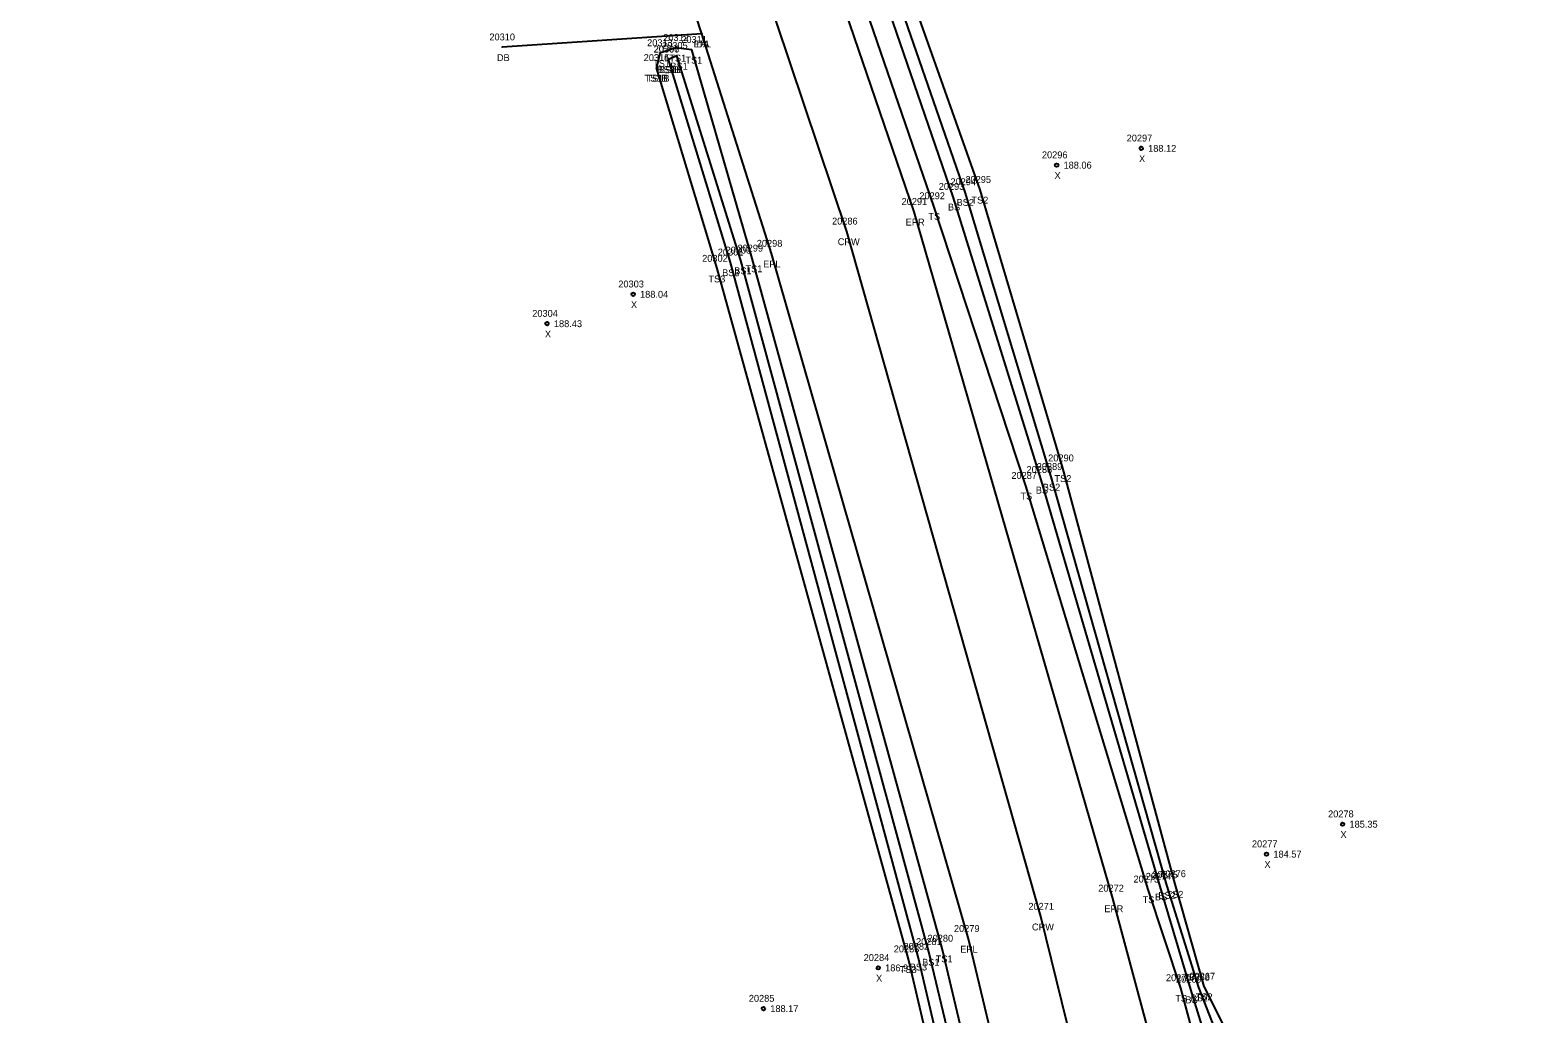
# Model space of a CAD drawing. Extents: x 2077883 to 2078272, y 787819 to 788945.
# Drawn here: x 2077915.3 to 2078134.4, y 788522.7 to 788665.6 of the extents above; entities that cross this region are included whole.
import ezdxf

# ---------------------------------------------------------------- set-up
doc = ezdxf.new("R2010")
doc.units = 0
for name, color, linetype in [('RD_DTM_BkLn1', 7, 'Continuous'), ('RD_DTM_BkLn2', 7, 'Continuous'), ('RD_EX_Driveway', 7, 'Continuous'), ('RD_EX_Driveway_txCode', 7, 'Continuous'), ('RD_EX_Road', 7, 'Continuous'), ('RD_EX_Road_txCode', 7, 'Continuous'), ('RD_Sketch8', 7, 'Continuous'), ('RD_SMD_Locator', 7, 'Continuous'), ('RD_SMD_Misc', 7, 'Continuous')]:
    doc.layers.add(name, color=color, linetype=linetype)

msp = doc.modelspace()

# ---------------------------------------------------------------- linework, layer by layer
at = {"layer": 'RD_DTM_BkLn1'}
msp.add_lwpolyline([(2078089.54, 788425.19), (2078086.71, 788437.21), (2078062.2, 788536.79), (2078033.97, 788636.37), (2078001.1, 788734.32), (2077964.77, 788830.93), (2077924.88, 788926.7)], dxfattribs=at)
at = {"layer": 'RD_DTM_BkLn2'}
for points in [[(2078132.44, 788472.19), (2078118.34, 788466.81), (2078100.1, 788488.15), (2078085.17, 788526.48), (2078080.48, 788541.38), (2078063.7, 788600.7), (2078051.16, 788642.09), (2078017.07, 788740.46), (2077982.21, 788837.85), (2077942.69, 788934.33)], [(2078130.39, 788474.32), (2078119.21, 788468.58), (2078104.21, 788490.29), (2078085.93, 788526.63), (2078081.69, 788541.53), (2078065.4, 788601.95), (2078053.34, 788642.42), (2078018.45, 788740.81), (2077983.36, 788838.44), (2077944.78, 788934.86)], [(2078134.43, 788470.29), (2078120, 788457.99), (2078107.89, 788457.91), (2078093.72, 788484.84), (2078082.52, 788526.41), (2078077.77, 788540.75), (2078060.01, 788599.41), (2078046.63, 788640.05), (2078012.72, 788738.62), (2077977.66, 788835.93), (2077936.62, 788932.18)], [(2078133.54, 788471.13), (2078119.08, 788459.82), (2078109.91, 788458.97), (2078096.37, 788486), (2078083.98, 788526.2), (2078079.55, 788541.15), (2078062.23, 788600.27), (2078049.45, 788641.41), (2078015.58, 788739.83), (2077979.12, 788836.63), (2077939.6, 788933.24)], [(2078073.43, 788440.66), (2078068.04, 788445.98), (2078067.07, 788450.97), (2078047.86, 788532.15), (2078020.2, 788632.44), (2078011.47, 788662.76), (2078009.13, 788663.05), (2078006.78, 788662.29), (2078006.29, 788660.13)], [(2078061.84, 788450.02), (2078042.92, 788530.6), (2078015.11, 788630.96), (2078006.29, 788660.13)], [(2078065.37, 788450.21), (2078045.88, 788531.66), (2078018.55, 788632.15), (2078009.27, 788661.89), (2078008.07, 788661.37)], [(2078065.33, 788432.61), (2078063.14, 788450.63), (2078044.34, 788530.97), (2078017.09, 788631.87), (2078008.07, 788661.37)]]:
    msp.add_lwpolyline(points, dxfattribs=at)
at = {"layer": 'RD_EX_Driveway'}
msp.add_line((2078012.91, 788665.11), (2077983.89, 788663.13), dxfattribs=at)
at = {"layer": 'RD_EX_Road'}
for points in [[(2078107.13, 788420.86), (2078105.11, 788427.29), (2078111.84, 788429.2), (2078117.69, 788434.7), (2078115.66, 788443.13), (2078106.49, 788447.64), (2078097.77, 788449.71), (2078094.97, 788456.34), (2078072.64, 788539.43), (2078043.77, 788639.22), (2078010.2, 788737.35), (2077974.01, 788834.54), (2077934.07, 788930.86)], [(2078107.13, 788420.86), (2078092.81, 788417.62), (2078089.54, 788425.19), (2078083.84, 788425.84), (2078081.3, 788430.73), (2078074.53, 788432.67), (2078073.43, 788440.66), (2078071.07, 788452.5), (2078051.67, 788533.56), (2078023.01, 788633.14), (2078012.91, 788665.11), (2078004.86, 788689.7), (2077990.53, 788730.26), (2077954.65, 788827.14), (2077915.26, 788922.36)]]:
    msp.add_lwpolyline(points, dxfattribs=at)
at = {"layer": 'RD_SMD_Locator'}
for centre, radius in [((2078012.91, 788665.11), 0.001), ((2078012.91, 788665.11), 0.001), ((2077983.89, 788663.13), 0.001), ((2078006.78, 788662.29), 0.001), ((2078009.13, 788663.05), 0.001), ((2078011.47, 788662.76), 0.001), ((2078006.29, 788660.13), 0.001), ((2078006.29, 788660.13), 0.001), ((2078008.07, 788661.37), 0.001), ((2078008.07, 788661.37), 0.001), ((2078009.27, 788661.89), 0.001), ((2078076.78, 788648.44), 0.25), ((2078064.48, 788646), 0.25), ((2078053.34, 788642.42), 0.001), ((2078049.45, 788641.41), 0.001), ((2078051.16, 788642.09), 0.001), ((2078043.77, 788639.22), 0.001), ((2078046.63, 788640.05), 0.001), ((2078033.97, 788636.37), 0.001), ((2078017.09, 788631.87), 0.001), ((2078018.55, 788632.15), 0.001), ((2078020.2, 788632.44), 0.001), ((2078023.01, 788633.14), 0.001), ((2078015.11, 788630.96), 0.001), ((2078002.92, 788627.23), 0.25), ((2077990.4, 788622.96), 0.25), ((2078063.7, 788600.7), 0.001), ((2078065.4, 788601.95), 0.001), ((2078060.01, 788599.41), 0.001), ((2078062.23, 788600.27), 0.001), ((2078106.05, 788550.22), 0.25), ((2078094.99, 788545.87), 0.25), ((2078081.69, 788541.53), 0.001), ((2078072.64, 788539.43), 0.001), ((2078077.77, 788540.75), 0.001), ((2078079.55, 788541.15), 0.001), ((2078080.48, 788541.38), 0.001), ((2078062.2, 788536.79), 0.001), ((2078051.67, 788533.56), 0.001), ((2078042.92, 788530.6), 0.001), ((2078044.34, 788530.97), 0.001), ((2078045.88, 788531.66), 0.001), ((2078047.86, 788532.15), 0.001), ((2078038.55, 788529.34), 0.25), ((2078082.52, 788526.41), 0.001), ((2078083.98, 788526.2), 0.001), ((2078085.17, 788526.48), 0.001), ((2078085.93, 788526.63), 0.001), ((2078021.85, 788523.42), 0.25)]:
    msp.add_circle(centre, radius, dxfattribs=at)

# ---------------------------------------------------------------- texts
at = {"layer": 'RD_EX_Driveway_txCode'}
for s, p in [('20310', (2077982.02, 788664.13)), ('DB', (2077983.11, 788661.13)), ('DA', (2078012.12, 788663.11))]:
    msp.add_text(s, height=1, dxfattribs=at).set_placement(p)
at = {"layer": 'RD_EX_Road_txCode'}
for s, p in [('EPL', (2078011.71, 788663.11)), ('20291', (2078041.94, 788640.22)), ('EPR', (2078042.54, 788637.22)), ('20298', (2078020.89, 788634.14)), ('EPL', (2078021.81, 788631.14)), ('20272', (2078070.53, 788540.43)), ('EPR', (2078071.42, 788537.43)), ('20279', (2078049.55, 788534.56)), ('EPL', (2078050.47, 788531.56))]:
    msp.add_text(s, height=1, dxfattribs=at).set_placement(p)
at = {"layer": 'RD_Sketch8'}
for s, p in [('20297', (2078074.66, 788649.44)), ('188.12', (2078077.78, 788647.94)), ('20296', (2078062.34, 788647)), ('X', (2078076.46, 788646.44)), ('X', (2078064.17, 788644)), ('188.06', (2078065.48, 788645.5)), ('20303', (2078000.76, 788628.23)), ('188.04', (2078003.92, 788626.73)), ('20304', (2077988.25, 788623.96)), ('X', (2078002.6, 788625.23)), ('188.43', (2077991.4, 788622.46)), ('X', (2077990.09, 788620.96)), ('20278', (2078103.94, 788551.22)), ('185.35', (2078107.05, 788549.72)), ('X', (2078105.74, 788548.22)), ('20277', (2078092.87, 788546.87)), ('184.57', (2078095.99, 788545.37)), ('X', (2078094.68, 788543.87)), ('20284', (2078036.43, 788530.34)), ('X', (2078038.23, 788527.34)), ('186.91', (2078039.55, 788528.84)), ('20285', (2078019.73, 788524.42)), ('188.17', (2078022.85, 788522.92))]:
    msp.add_text(s, height=1, dxfattribs=at).set_placement(p)
at = {"layer": 'RD_SMD_Misc'}
for s, p in [('20313', (2078004.95, 788663.29)), ('20312', (2078007.29, 788664.05)), ('20311', (2078009.92, 788663.76)), ('20314', (2078004.45, 788661.13)), ('20315', (2078004.45, 788661.13)), ('20306', (2078005.89, 788662.37)), ('20307', (2078005.92, 788662.37)), ('20305', (2078007.12, 788662.89)), ('TS1', (2078008.17, 788661.05)), ('TS1', (2078005.82, 788660.29)), ('BS3B', (2078006.37, 788659.37)), ('BS1B', (2078006.66, 788659.37)), ('BS1', (2078008.33, 788659.89)), ('TS1', (2078010.51, 788660.76)), ('TS3B', (2078004.57, 788658.13)), ('TS1B', (2078004.86, 788658.13)), ('20293', (2078047.34, 788642.41)), ('20294', (2078049.04, 788643.09)), ('20295', (2078051.22, 788643.42)), ('20292', (2078044.52, 788641.05)), ('BS', (2078048.67, 788639.41)), ('BS2', (2078049.93, 788640.09)), ('TS2', (2078052.09, 788640.42)), ('20286', (2078031.83, 788637.37)), ('TS', (2078045.84, 788638.05)), ('20301', (2078015.22, 788632.87)), ('20300', (2078016.35, 788633.15)), ('20299', (2078018.08, 788633.44)), ('CRW', (2078032.66, 788634.37)), ('20302', (2078012.95, 788631.96)), ('TS1', (2078019.24, 788630.44)), ('TS3', (2078013.86, 788628.96)), ('BS3', (2078015.86, 788629.87)), ('BS1', (2078017.61, 788630.15)), ('20290', (2078063.25, 788602.95)), ('20287', (2078057.9, 788600.41)), ('20288', (2078060.11, 788601.27)), ('20289', (2078061.58, 788601.7)), ('TS2', (2078064.16, 788599.95)), ('TS', (2078059.22, 788597.41)), ('BS', (2078061.45, 788598.27)), ('BS2', (2078062.47, 788598.7)), ('20273', (2078075.65, 788541.75)), ('20274', (2078077.43, 788542.15)), ('20275', (2078078.36, 788542.38)), ('20276', (2078079.55, 788542.53)), ('TS', (2078076.98, 788538.75)), ('BS', (2078078.77, 788539.15)), ('BS2', (2078079.25, 788539.38)), ('TS2', (2078080.45, 788539.53)), ('20271', (2078060.37, 788537.79)), ('CRW', (2078060.89, 788534.79)), ('20282', (2078042.22, 788531.97)), ('20281', (2078044.04, 788532.66)), ('20280', (2078045.71, 788533.15)), ('20283', (2078040.8, 788531.6)), ('BS1', (2078044.93, 788529.66)), ('TS1', (2078046.9, 788530.15)), ('TS3', (2078041.68, 788528.6)), ('BS3', (2078043.11, 788528.97)), ('20270', (2078080.37, 788527.41)), ('20268', (2078083.03, 788527.48)), ('20267', (2078083.79, 788527.63)), ('20269', (2078081.83, 788527.2)), ('TS', (2078081.73, 788524.41)), ('BS', (2078083.2, 788524.2)), ('BS2', (2078083.94, 788524.48)), ('TS2', (2078084.69, 788524.63))]:
    msp.add_text(s, height=1, dxfattribs=at).set_placement(p)

doc.saveas('drawing.dxf')
